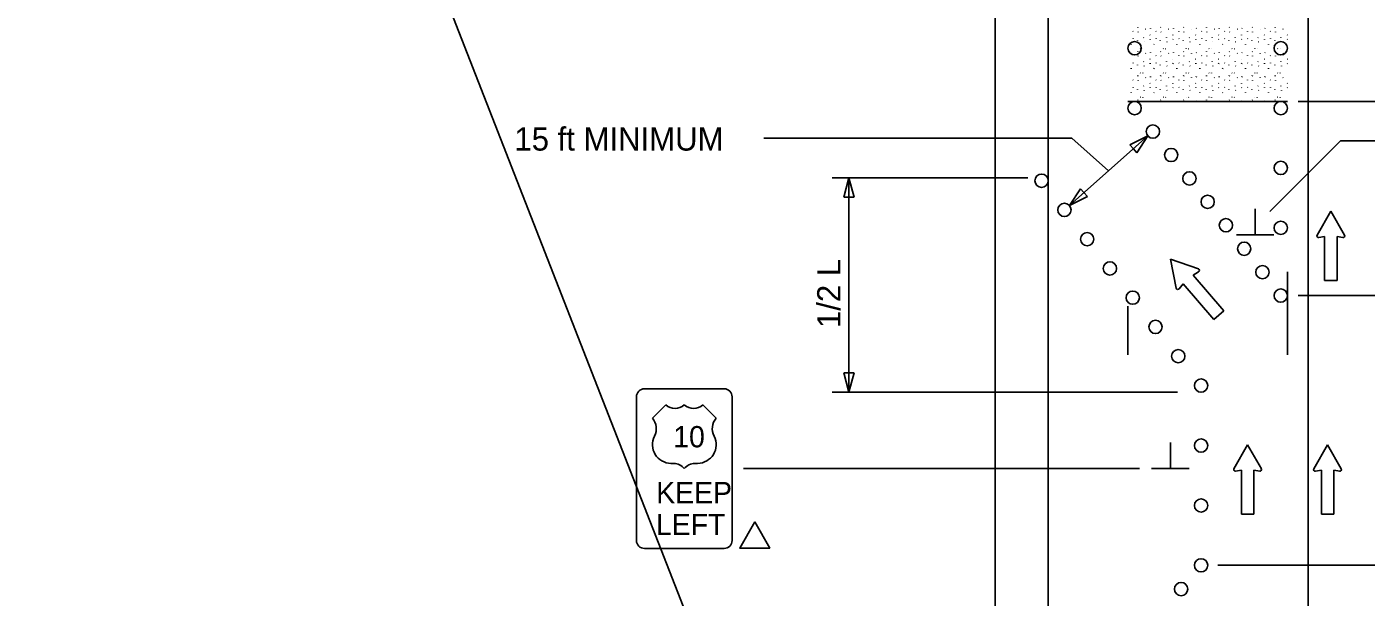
# Model space of a CAD drawing. Extents: x 16519 to 19508, y 5743 to 6974.
# Drawn here: x 16595 to 16998.2, y 6297.4 to 6469 of the extents above; entities that cross this region are included whole.
import ezdxf

# ---------------------------------------------------------------- set-up
doc = ezdxf.new("R2010")
doc.units = 0
for name, color, linetype in [('ALI_LEGAL_EX', 7, 'Continuous'), ('MT_SCRATCH_LEVEL_A', 7, 'Continuous'), ('MT_SCRATCH_LEVEL_E', 7, 'Continuous'), ('PAVT_EDGE_EX', 7, 'Continuous'), ('TRAFFIC_SIGNS_PR', 7, 'Continuous'), ('TYPICAL_EX', 7, 'Continuous'), ('TYPICAL_TEXT_DIMEN_PR', 7, 'Continuous')]:
    doc.layers.add(name, color=color, linetype=linetype)

msp = doc.modelspace()

# ---------------------------------------------------------------- linework, layer by layer
at = {"layer": 'ALI_LEGAL_EX'}
for p, q in [((16980.68, 6974.12), (16980.68, 6155.98)), ((16980.68, 6922.21), (16980.68, 6058.3)), ((16594.98, 6800.51), (16817, 6232.14))]:
    msp.add_line(p, q, dxfattribs=at)
for points in [[(16974.45, 6370.33), (16974.45, 6395.33)], [(16926.45, 6370.33), (16926.45, 6384.97)]]:
    msp.add_lwpolyline(points, dxfattribs=at)
at = {"layer": 'MT_SCRATCH_LEVEL_A'}
for p, q in [((16927.94, 6467.62), (16927.99, 6467.55)), ((16929.39, 6468.75), (16929.44, 6468.87)), ((16929.47, 6467.49), (16929.53, 6467.41)), ((16931.76, 6468.3), (16931.81, 6468.23)), ((16933.21, 6468.45), (16933.26, 6468.57)), ((16934.83, 6467.62), (16934.88, 6467.55)), ((16936.28, 6468.75), (16936.33, 6468.87)), ((16936.36, 6467.49), (16936.41, 6467.41)), ((16938.65, 6468.3), (16938.7, 6468.23)), ((16940.1, 6468.45), (16940.15, 6468.57)), ((16941.72, 6467.62), (16941.77, 6467.55)), ((16943.17, 6468.75), (16943.22, 6468.87)), ((16943.25, 6467.49), (16943.3, 6467.41)), ((16945.54, 6468.3), (16945.59, 6468.23)), ((16946.99, 6468.45), (16947.04, 6468.57)), ((16948.61, 6467.62), (16948.66, 6467.55)), ((16950.06, 6468.75), (16950.11, 6468.87)), ((16950.14, 6467.49), (16950.19, 6467.41)), ((16952.42, 6468.3), (16952.48, 6468.23)), ((16953.88, 6468.45), (16953.93, 6468.57)), ((16955.49, 6467.62), (16955.55, 6467.55)), ((16956.94, 6468.75), (16956.99, 6468.87)), ((16957.02, 6467.49), (16957.08, 6467.41)), ((16959.31, 6468.3), (16959.37, 6468.23)), ((16960.76, 6468.45), (16960.81, 6468.57)), ((16962.38, 6467.62), (16962.43, 6467.55)), ((16963.83, 6468.75), (16963.88, 6468.87)), ((16963.91, 6467.49), (16963.96, 6467.41)), ((16966.2, 6468.3), (16966.25, 6468.23)), ((16967.65, 6468.45), (16967.7, 6468.57)), ((16969.27, 6467.62), (16969.32, 6467.55)), ((16970.72, 6468.75), (16970.77, 6468.87)), ((16970.8, 6467.49), (16970.85, 6467.41)), ((16973.09, 6468.3), (16973.14, 6468.23)), ((16927.37, 6463.66), (16927.42, 6463.78)), ((16927.99, 6465.42), (16928.04, 6465.34)), ((16929.27, 6464.84), (16929.29, 6464.72)), ((16931.12, 6465.7), (16931.17, 6465.81)), ((16931.3, 6464.5), (16931.35, 6464.42)), ((16933.04, 6466.57), (16933.09, 6466.49)), ((16933.08, 6465.16), (16933.13, 6465.28)), ((16934.26, 6463.66), (16934.31, 6463.78)), ((16934.88, 6465.42), (16934.93, 6465.34)), ((16936.16, 6464.84), (16936.17, 6464.72)), ((16938, 6465.7), (16938.05, 6465.81)), ((16938.19, 6464.5), (16938.24, 6464.42)), ((16939.93, 6466.57), (16939.98, 6466.49)), ((16939.97, 6465.16), (16940.02, 6465.28)), ((16941.15, 6463.66), (16941.2, 6463.78)), ((16941.77, 6465.42), (16941.82, 6465.34)), ((16943.05, 6464.84), (16943.06, 6464.72)), ((16944.89, 6465.7), (16944.94, 6465.81)), ((16945.08, 6464.5), (16945.13, 6464.42)), ((16946.81, 6466.57), (16946.87, 6466.49)), ((16946.86, 6465.16), (16946.91, 6465.28)), ((16948.04, 6463.66), (16948.09, 6463.78)), ((16948.65, 6465.42), (16948.71, 6465.34)), ((16949.94, 6464.84), (16949.95, 6464.72)), ((16951.78, 6465.7), (16951.83, 6465.81)), ((16951.97, 6464.5), (16952.02, 6464.42)), ((16953.7, 6466.57), (16953.75, 6466.49)), ((16953.74, 6465.16), (16953.8, 6465.28)), ((16954.92, 6463.66), (16954.97, 6463.78)), ((16955.54, 6465.42), (16955.59, 6465.34)), ((16956.82, 6464.84), (16956.84, 6464.72)), ((16958.67, 6465.7), (16958.72, 6465.81)), ((16958.85, 6464.5), (16958.9, 6464.42)), ((16960.59, 6466.57), (16960.64, 6466.49)), ((16960.63, 6465.16), (16960.69, 6465.28)), ((16961.81, 6463.66), (16961.86, 6463.78)), ((16962.43, 6465.42), (16962.48, 6465.34)), ((16963.71, 6464.84), (16963.72, 6464.72)), ((16965.55, 6465.7), (16965.6, 6465.81)), ((16965.74, 6464.5), (16965.79, 6464.42)), ((16967.48, 6466.57), (16967.53, 6466.49)), ((16967.52, 6465.16), (16967.57, 6465.28)), ((16968.7, 6463.66), (16968.75, 6463.78)), ((16969.32, 6465.42), (16969.37, 6465.34)), ((16970.6, 6464.84), (16970.61, 6464.72)), ((16972.44, 6465.7), (16972.49, 6465.81)), ((16972.63, 6464.5), (16972.68, 6464.42)), ((16974.37, 6466.57), (16974.42, 6466.49)), ((16974.41, 6465.16), (16974.45, 6465.25)), ((16929.39, 6461.47), (16929.44, 6461.58)), ((16929.47, 6460.2), (16929.53, 6460.12)), ((16930.16, 6462.43), (16930.21, 6462.35)), ((16930.89, 6462.4), (16930.95, 6462.32)), ((16931.76, 6461.02), (16931.81, 6460.94)), ((16933.04, 6459.28), (16933.09, 6459.2)), ((16933.21, 6461.17), (16933.26, 6461.28)), ((16934.83, 6460.34), (16934.88, 6460.26)), ((16936.28, 6461.47), (16936.33, 6461.58)), ((16936.36, 6460.2), (16936.41, 6460.12)), ((16937.05, 6462.43), (16937.1, 6462.35)), ((16937.78, 6462.4), (16937.83, 6462.32)), ((16938.65, 6461.02), (16938.7, 6460.94)), ((16939.93, 6459.28), (16939.98, 6459.2)), ((16940.1, 6461.17), (16940.15, 6461.28)), ((16941.72, 6460.34), (16941.77, 6460.26)), ((16943.17, 6461.47), (16943.22, 6461.58)), ((16943.25, 6460.2), (16943.3, 6460.12)), ((16943.93, 6462.43), (16943.98, 6462.35)), ((16944.67, 6462.4), (16944.72, 6462.32)), ((16945.54, 6461.02), (16945.59, 6460.94)), ((16946.81, 6459.28), (16946.87, 6459.2)), ((16946.99, 6461.17), (16947.04, 6461.28)), ((16948.61, 6460.34), (16948.66, 6460.26)), ((16950.06, 6461.47), (16950.11, 6461.58)), ((16950.14, 6460.2), (16950.19, 6460.12)), ((16950.82, 6462.43), (16950.87, 6462.35)), ((16951.56, 6462.4), (16951.61, 6462.32)), ((16952.42, 6461.02), (16952.48, 6460.94)), ((16953.7, 6459.28), (16953.75, 6459.2)), ((16953.88, 6461.17), (16953.93, 6461.28)), ((16955.49, 6460.34), (16955.55, 6460.26)), ((16956.94, 6461.47), (16956.99, 6461.58)), ((16957.02, 6460.2), (16957.08, 6460.12)), ((16957.71, 6462.43), (16957.76, 6462.35)), ((16958.44, 6462.4), (16958.5, 6462.32)), ((16959.31, 6461.02), (16959.37, 6460.94)), ((16960.59, 6459.28), (16960.64, 6459.2)), ((16960.76, 6461.17), (16960.81, 6461.28)), ((16962.38, 6460.34), (16962.43, 6460.26)), ((16963.83, 6461.47), (16963.88, 6461.58)), ((16963.91, 6460.2), (16963.96, 6460.12)), ((16964.6, 6462.43), (16964.65, 6462.35)), ((16965.33, 6462.4), (16965.38, 6462.32)), ((16966.2, 6461.02), (16966.25, 6460.94)), ((16967.48, 6459.28), (16967.53, 6459.2)), ((16967.65, 6461.17), (16967.7, 6461.28)), ((16969.27, 6460.34), (16969.32, 6460.26)), ((16970.72, 6461.47), (16970.77, 6461.58)), ((16970.8, 6460.2), (16970.85, 6460.12)), ((16971.48, 6462.43), (16971.53, 6462.35)), ((16972.22, 6462.4), (16972.27, 6462.32)), ((16973.09, 6461.02), (16973.14, 6460.94)), ((16974.37, 6459.28), (16974.42, 6459.2)), ((16927.37, 6456.38), (16927.42, 6456.49)), ((16927.99, 6458.13), (16928.04, 6458.05)), ((16929.27, 6457.56), (16929.29, 6457.44)), ((16930.16, 6455.14), (16930.21, 6455.06)), ((16930.89, 6455.11), (16930.95, 6455.03)), ((16931.12, 6458.41), (16931.17, 6458.53)), ((16931.3, 6457.21), (16931.35, 6457.13)), ((16933.08, 6457.88), (16933.13, 6458)), ((16934.26, 6456.38), (16934.31, 6456.49)), ((16934.88, 6458.13), (16934.93, 6458.05)), ((16936.16, 6457.56), (16936.17, 6457.44)), ((16937.05, 6455.14), (16937.1, 6455.06)), ((16937.78, 6455.11), (16937.83, 6455.03)), ((16938, 6458.41), (16938.05, 6458.53)), ((16938.19, 6457.21), (16938.24, 6457.13)), ((16939.97, 6457.88), (16940.02, 6458)), ((16941.15, 6456.38), (16941.2, 6456.49)), ((16941.77, 6458.13), (16941.82, 6458.05)), ((16943.05, 6457.56), (16943.06, 6457.44)), ((16943.93, 6455.14), (16943.98, 6455.06)), ((16944.67, 6455.11), (16944.72, 6455.03)), ((16944.89, 6458.41), (16944.94, 6458.53)), ((16945.08, 6457.21), (16945.13, 6457.13)), ((16946.86, 6457.88), (16946.91, 6458)), ((16948.04, 6456.38), (16948.09, 6456.49)), ((16948.65, 6458.13), (16948.71, 6458.05)), ((16949.94, 6457.56), (16949.95, 6457.44)), ((16950.82, 6455.14), (16950.87, 6455.06)), ((16951.56, 6455.11), (16951.61, 6455.03)), ((16951.78, 6458.41), (16951.83, 6458.53)), ((16951.97, 6457.21), (16952.02, 6457.13)), ((16953.74, 6457.88), (16953.8, 6458)), ((16954.92, 6456.38), (16954.97, 6456.49)), ((16955.54, 6458.13), (16955.59, 6458.05)), ((16956.82, 6457.56), (16956.84, 6457.44)), ((16957.71, 6455.14), (16957.76, 6455.06)), ((16958.44, 6455.11), (16958.5, 6455.03)), ((16958.67, 6458.41), (16958.72, 6458.53)), ((16958.85, 6457.21), (16958.9, 6457.13)), ((16960.63, 6457.88), (16960.69, 6458)), ((16961.81, 6456.38), (16961.86, 6456.49)), ((16962.43, 6458.13), (16962.48, 6458.05)), ((16963.71, 6457.56), (16963.72, 6457.44)), ((16964.6, 6455.14), (16964.65, 6455.06)), ((16965.33, 6455.11), (16965.38, 6455.03)), ((16965.55, 6458.41), (16965.6, 6458.53)), ((16965.74, 6457.21), (16965.79, 6457.13)), ((16967.52, 6457.88), (16967.57, 6458)), ((16968.7, 6456.38), (16968.75, 6456.49)), ((16969.32, 6458.13), (16969.37, 6458.05)), ((16970.6, 6457.56), (16970.61, 6457.44)), ((16971.48, 6455.14), (16971.53, 6455.06)), ((16972.22, 6455.11), (16972.27, 6455.03)), ((16972.44, 6458.41), (16972.49, 6458.53)), ((16972.63, 6457.21), (16972.68, 6457.13)), ((16974.41, 6457.88), (16974.45, 6457.97)), ((16927.94, 6453.06), (16927.99, 6452.98)), ((16927.99, 6450.85), (16928.04, 6450.77)), ((16929.39, 6454.18), (16929.44, 6454.3)), ((16929.47, 6452.91), (16929.53, 6452.84)), ((16931.12, 6451.13), (16931.17, 6451.24)), ((16931.76, 6453.73), (16931.81, 6453.65)), ((16933.04, 6452), (16933.09, 6451.92)), ((16933.21, 6453.88), (16933.26, 6454)), ((16934.83, 6453.06), (16934.88, 6452.98)), ((16934.88, 6450.85), (16934.93, 6450.77)), ((16936.28, 6454.18), (16936.33, 6454.3)), ((16936.36, 6452.91), (16936.41, 6452.84)), ((16938, 6451.13), (16938.05, 6451.24)), ((16938.65, 6453.73), (16938.7, 6453.65)), ((16939.93, 6452), (16939.98, 6451.92)), ((16940.1, 6453.88), (16940.15, 6454)), ((16941.72, 6453.06), (16941.77, 6452.98)), ((16941.77, 6450.85), (16941.82, 6450.77)), ((16943.17, 6454.18), (16943.22, 6454.3)), ((16943.25, 6452.91), (16943.3, 6452.84)), ((16944.89, 6451.13), (16944.94, 6451.24)), ((16945.54, 6453.73), (16945.59, 6453.65)), ((16946.81, 6452), (16946.87, 6451.92)), ((16946.99, 6453.88), (16947.04, 6454)), ((16948.61, 6453.06), (16948.66, 6452.98)), ((16948.65, 6450.85), (16948.71, 6450.77)), ((16950.06, 6454.18), (16950.11, 6454.3)), ((16950.14, 6452.91), (16950.19, 6452.84)), ((16951.78, 6451.13), (16951.83, 6451.24)), ((16952.42, 6453.73), (16952.48, 6453.65)), ((16953.7, 6452), (16953.75, 6451.92)), ((16953.88, 6453.88), (16953.93, 6454)), ((16955.49, 6453.06), (16955.55, 6452.98)), ((16955.54, 6450.85), (16955.59, 6450.77)), ((16956.94, 6454.18), (16956.99, 6454.3)), ((16957.02, 6452.91), (16957.08, 6452.84)), ((16958.67, 6451.13), (16958.72, 6451.24)), ((16959.31, 6453.73), (16959.37, 6453.65)), ((16960.59, 6452), (16960.64, 6451.92)), ((16960.76, 6453.88), (16960.81, 6454)), ((16962.38, 6453.06), (16962.43, 6452.98)), ((16962.43, 6450.85), (16962.48, 6450.77)), ((16963.83, 6454.18), (16963.88, 6454.3)), ((16963.91, 6452.91), (16963.96, 6452.84)), ((16965.55, 6451.13), (16965.6, 6451.24)), ((16966.2, 6453.73), (16966.25, 6453.65)), ((16967.48, 6452), (16967.53, 6451.92)), ((16967.65, 6453.88), (16967.7, 6454)), ((16969.27, 6453.06), (16969.32, 6452.98)), ((16969.32, 6450.85), (16969.37, 6450.77)), ((16970.72, 6454.18), (16970.77, 6454.3)), ((16970.8, 6452.91), (16970.85, 6452.84)), ((16972.44, 6451.13), (16972.49, 6451.24)), ((16973.09, 6453.73), (16973.14, 6453.65)), ((16974.37, 6452), (16974.42, 6451.92)), ((16927.37, 6449.09), (16927.42, 6449.21)), ((16929.27, 6450.27), (16929.29, 6450.15)), ((16929.39, 6446.9), (16929.44, 6447.01)), ((16930.16, 6447.86), (16930.21, 6447.78)), ((16930.89, 6447.83), (16930.95, 6447.75)), ((16931.3, 6449.93), (16931.35, 6449.85)), ((16933.08, 6450.6), (16933.13, 6450.71)), ((16934.26, 6449.09), (16934.31, 6449.21)), ((16936.16, 6450.27), (16936.17, 6450.15)), ((16936.28, 6446.9), (16936.33, 6447.01)), ((16937.05, 6447.86), (16937.1, 6447.78)), ((16937.78, 6447.83), (16937.83, 6447.75)), ((16938.19, 6449.93), (16938.24, 6449.85)), ((16939.97, 6450.6), (16940.02, 6450.71)), ((16941.15, 6449.09), (16941.2, 6449.21)), ((16943.05, 6450.27), (16943.06, 6450.15)), ((16943.17, 6446.9), (16943.22, 6447.01)), ((16943.93, 6447.86), (16943.98, 6447.78)), ((16944.67, 6447.83), (16944.72, 6447.75)), ((16945.08, 6449.93), (16945.13, 6449.85)), ((16946.86, 6450.6), (16946.91, 6450.71)), ((16948.04, 6449.09), (16948.09, 6449.21)), ((16949.94, 6450.27), (16949.95, 6450.15)), ((16950.06, 6446.9), (16950.11, 6447.01)), ((16950.82, 6447.86), (16950.87, 6447.78)), ((16951.56, 6447.83), (16951.61, 6447.75)), ((16951.97, 6449.93), (16952.02, 6449.85)), ((16953.74, 6450.6), (16953.8, 6450.71)), ((16954.92, 6449.09), (16954.97, 6449.21)), ((16956.82, 6450.27), (16956.84, 6450.15)), ((16956.94, 6446.9), (16956.99, 6447.01)), ((16957.71, 6447.86), (16957.76, 6447.78)), ((16958.44, 6447.83), (16958.5, 6447.75)), ((16958.85, 6449.93), (16958.9, 6449.85)), ((16960.63, 6450.6), (16960.69, 6450.71)), ((16961.81, 6449.09), (16961.86, 6449.21)), ((16963.71, 6450.27), (16963.72, 6450.15)), ((16963.83, 6446.9), (16963.88, 6447.01)), ((16964.6, 6447.86), (16964.65, 6447.78)), ((16965.33, 6447.83), (16965.38, 6447.75)), ((16965.74, 6449.93), (16965.79, 6449.85)), ((16967.52, 6450.6), (16967.57, 6450.71)), ((16968.7, 6449.09), (16968.75, 6449.21)), ((16970.6, 6450.27), (16970.61, 6450.15)), ((16970.72, 6446.9), (16970.77, 6447.01)), ((16971.48, 6447.86), (16971.53, 6447.78)), ((16972.22, 6447.83), (16972.27, 6447.75)), ((16972.63, 6449.93), (16972.68, 6449.85)), ((16974.41, 6450.6), (16974.45, 6450.68)), ((16974.45, 6446.53), (16926.45, 6446.53)), ((16926.45, 6446.53), (16974.45, 6446.53)), ((16933.21, 6446.6), (16933.26, 6446.72)), ((16940.1, 6446.6), (16940.15, 6446.72)), ((16946.99, 6446.6), (16947.04, 6446.72)), ((16953.88, 6446.6), (16953.93, 6446.72)), ((16960.76, 6446.6), (16960.81, 6446.72)), ((16967.65, 6446.6), (16967.7, 6446.72))]:
    msp.add_line(p, q, dxfattribs=at)
at = {"layer": 'MT_SCRATCH_LEVEL_E'}
for p, q in [((16987.48, 6413.53), (16983.37, 6406.28)), ((16991.62, 6406.28), (16987.48, 6413.53)), ((16983.85, 6405.6), (16985.63, 6405.92)), ((16985.63, 6405.92), (16985.63, 6392.66)), ((16989.37, 6392.66), (16989.37, 6405.92)), ((16989.37, 6405.92), (16991.15, 6405.6)), ((16985.63, 6392.66), (16989.37, 6392.66)), ((16962.45, 6343.28), (16958.33, 6336.04)), ((16962.45, 6343.28), (16958.33, 6336.04)), ((16966.59, 6336.04), (16962.45, 6343.28)), ((16966.59, 6336.04), (16962.45, 6343.28)), ((16986.5, 6343.28), (16982.39, 6336.04)), ((16986.5, 6343.28), (16982.39, 6336.04)), ((16990.65, 6336.04), (16986.5, 6343.28)), ((16990.65, 6336.04), (16986.5, 6343.28)), ((16958.82, 6335.36), (16960.59, 6335.67)), ((16958.82, 6335.36), (16960.59, 6335.67)), ((16960.59, 6335.67), (16960.59, 6322.41)), ((16960.59, 6335.67), (16960.59, 6322.41)), ((16964.34, 6322.41), (16964.34, 6335.67)), ((16964.34, 6335.67), (16966.11, 6335.36)), ((16964.34, 6322.41), (16964.34, 6335.67)), ((16964.34, 6335.67), (16966.11, 6335.36)), ((16982.87, 6335.36), (16984.65, 6335.67)), ((16982.87, 6335.36), (16984.65, 6335.67)), ((16984.65, 6335.67), (16984.65, 6322.41)), ((16984.65, 6335.67), (16984.65, 6322.41)), ((16988.39, 6322.41), (16988.39, 6335.67)), ((16988.39, 6335.67), (16990.17, 6335.36)), ((16988.39, 6322.41), (16988.39, 6335.67)), ((16988.39, 6335.67), (16990.17, 6335.36)), ((16960.59, 6322.41), (16964.34, 6322.41)), ((16960.59, 6322.41), (16964.34, 6322.41)), ((16984.65, 6322.41), (16988.39, 6322.41)), ((16984.65, 6322.41), (16988.39, 6322.41))]:
    msp.add_line(p, q, dxfattribs=at)
for centre, start, end in [((16983.77, 6406.06), 150.4248, 279.9638), ((16991.22, 6406.06), 260.0362, 29.7731), ((16958.74, 6335.81), 150.4248, 279.9638), ((16958.74, 6335.81), 150.4248, 279.9638), ((16966.18, 6335.81), 260.0362, 29.7731), ((16966.18, 6335.81), 260.0362, 29.7731), ((16982.8, 6335.81), 150.4248, 279.9638), ((16982.8, 6335.81), 150.4248, 279.9638), ((16990.24, 6335.81), 260.0362, 29.7731), ((16990.24, 6335.81), 260.0362, 29.7731)]:
    msp.add_arc(centre, 0.463, start, end, dxfattribs=at)
at = {"layer": 'PAVT_EDGE_EX'}
for p, q in [((16886.45, 6480.53), (16886.45, 6125.9)), ((16902.45, 6480.53), (16902.45, 6125.9))]:
    msp.add_line(p, q, dxfattribs=at)
at = {"layer": 'TRAFFIC_SIGNS_PR'}
for p, q in [((16804.9, 6360.11), (16780.9, 6360.11)), ((16778.5, 6357.71), (16778.5, 6314.51)), ((16807.3, 6314.51), (16807.3, 6357.71)), ((16780.9, 6312.11), (16804.9, 6312.11))]:
    msp.add_line(p, q, dxfattribs=at)
for centre in [(16928.45, 6462.53), (16972.44, 6462.53), (16928.45, 6444.53), (16928.45, 6444.53), (16972.44, 6444.53), (16933.95, 6437.48), (16939.44, 6430.43), (16972.44, 6426.53), (16900.45, 6422.7), (16944.94, 6423.38), (16907.3, 6413.9), (16950.43, 6416.34), (16955.93, 6409.29), (16972.44, 6408.53), (16914.16, 6405.11), (16961.42, 6402.24), (16921.02, 6396.31), (16966.92, 6395.19), (16927.87, 6387.52), (16972.42, 6388.14), (16934.73, 6378.72), (16941.59, 6369.93), (16948.44, 6361.08), (16948.44, 6343.03), (16948.44, 6325.03), (16948.44, 6307.03), (16942.44, 6299.89)]:
    msp.add_circle(centre, 2, dxfattribs=at)
for centre, start, end in [((16780.9, 6357.71), 90, 180), ((16804.9, 6357.71), 0, 90), ((16780.9, 6314.51), 180, 270), ((16804.9, 6314.51), 270, 0)]:
    msp.add_arc(centre, 2.4, start, end, dxfattribs=at)
at = {"layer": 'TYPICAL_EX'}
for p, q in [((16783.3, 6351.31), (16787.3, 6355.31)), ((16802.5, 6351.31), (16798.5, 6355.31)), ((16788.89, 6337.7), (16789.69, 6337.7)), ((16796.9, 6337.7), (16796.1, 6337.7))]:
    msp.add_line(p, q, dxfattribs=at)
for centre, radius, start, end in [((16790.1, 6358.22), 4.04, 226.1404, 313.8596), ((16795.7, 6358.22), 4.04, 226.1404, 313.8596), ((16779.5, 6348.1), 4.96, 333.0977, 40.1936), ((16806.29, 6348.1), 4.96, 139.8064, 206.9023), ((16788.9, 6343.29), 5.59, 152.6698, 269.9013), ((16796.89, 6343.29), 5.59, 270.0987, 27.3302), ((16789.7, 6333.69), 4.01, 37.1038, 90.1385), ((16796.09, 6333.69), 4.01, 89.8615, 142.8962)]:
    msp.add_arc(centre, radius, start, end, dxfattribs=at)
at = {"layer": 'TYPICAL_TEXT_DIMEN_PR'}
for p, q in [((16977.64, 6446.53), (17063.45, 6446.53)), ((16816.88, 6435.45), (16909.5, 6435.45)), ((16932.45, 6436.16), (16908.8, 6415.23)), ((16920.63, 6425.69), (16909.5, 6435.45)), ((16927.02, 6433.45), (16932.45, 6436.16)), ((16932.45, 6436.16), (16929.1, 6431.1)), ((16969.12, 6413.48), (16990.46, 6434.68)), ((17054.35, 6434.68), (16990.46, 6434.68)), ((16928.06, 6432.27), (16927.02, 6433.45)), ((16929.1, 6431.1), (16928.06, 6432.27)), ((16837.45, 6423.59), (16896.35, 6423.59)), ((16840.88, 6417.73), (16842.45, 6423.59)), ((16842.45, 6423.59), (16842.45, 6359.08)), ((16842.45, 6423.59), (16844.02, 6417.73)), ((16908.8, 6415.23), (16912.15, 6420.29)), ((16912.15, 6420.29), (16913.19, 6419.11)), ((16913.19, 6419.11), (16914.23, 6417.94)), ((16842.45, 6417.73), (16840.88, 6417.73)), ((16844.02, 6417.73), (16842.45, 6417.73)), ((16914.23, 6417.94), (16908.8, 6415.23)), ((16964.72, 6406.41), (16964.72, 6414.19)), ((16970.35, 6406.41), (16959.1, 6406.41)), ((16947.63, 6396.15), (16939.24, 6399.11)), ((16939.24, 6399.11), (16940.96, 6390.4)), ((16946.07, 6394.28), (16947.72, 6395.26)), ((16941.83, 6390.18), (16943.04, 6391.67)), ((16943.04, 6391.67), (16952.27, 6380.96)), ((16955.3, 6383.57), (16946.07, 6394.28)), ((17093.24, 6388.14), (16977.64, 6388.14)), ((16952.27, 6380.96), (16955.3, 6383.57)), ((16842.45, 6359.08), (16840.88, 6364.94)), ((16840.88, 6364.94), (16842.45, 6364.94)), ((16842.45, 6364.94), (16844.02, 6364.94)), ((16844.02, 6364.94), (16842.45, 6359.08)), ((16941.33, 6359.08), (16837.45, 6359.08)), ((16939.2, 6336.14), (16939.2, 6343.92)), ((16810.72, 6336.14), (16929.95, 6336.14)), ((16944.82, 6336.14), (16933.57, 6336.14)), ((16953.49, 6307.03), (17093.24, 6307.03))]:
    msp.add_line(p, q, dxfattribs=at)
msp.add_lwpolyline([(16814.12, 6320.07), (16809.59, 6312.23), (16818.64, 6312.23)], close=True, dxfattribs=at)
for centre, start, end in [((16947.46, 6395.68), 300.7803, 70.5173), ((16941.45, 6390.5), 191.169, 320.708)]:
    msp.add_arc(centre, 0.494, start, end, dxfattribs=at)

# ---------------------------------------------------------------- texts
at = {"layer": 'TRAFFIC_SIGNS_PR'}
for s, p in [('10', (16789.56, 6342.51)), ('KEEP', (16784.43, 6325.71)), ('LEFT', (16784.35, 6316.11))]:
    msp.add_text(s, height=6.4, dxfattribs=at).set_placement(p)
at = {"layer": 'TYPICAL_TEXT_DIMEN_PR'}
msp.add_text('15 ft MINIMUM', height=7, dxfattribs=at).set_placement((16741.76, 6431.75))
msp.add_text('1/2 L', height=7, rotation=90, dxfattribs=at).set_placement((16839.89, 6378.38))

doc.saveas('drawing.dxf')
